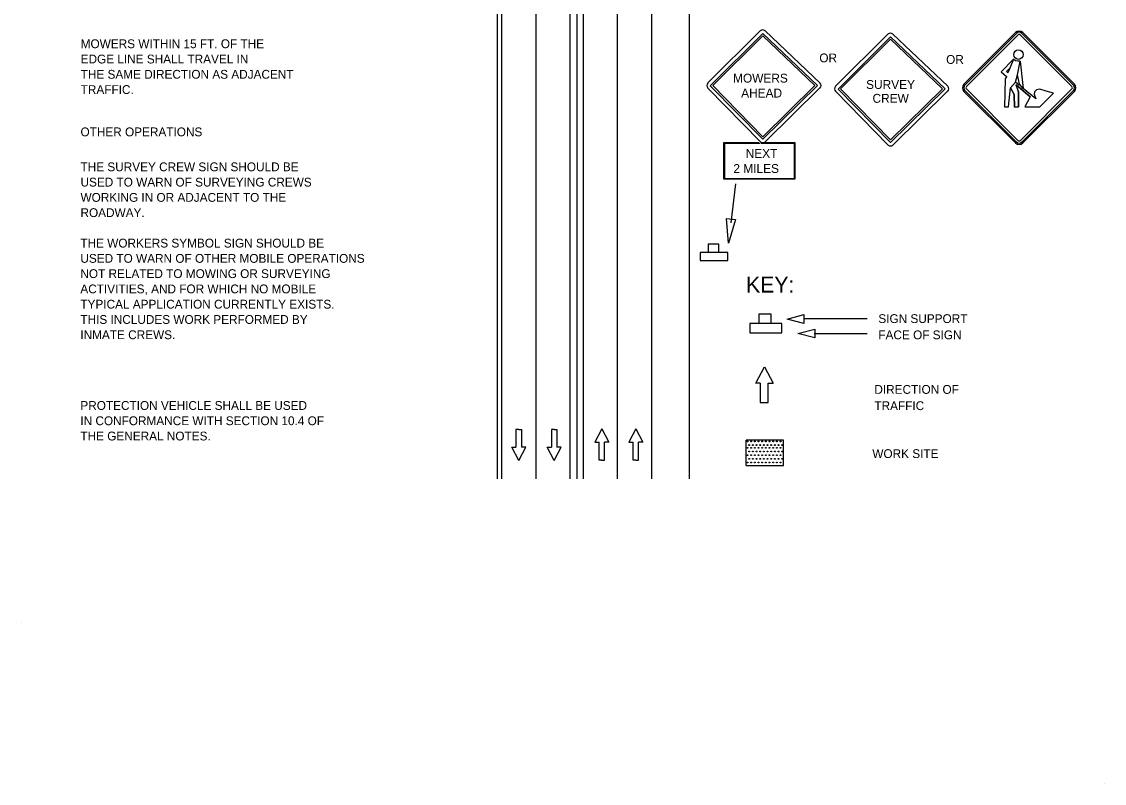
# Model space of a CAD drawing. Extents: x 612.48 to 619.85, y 611.03 to 621.01.
# Drawn here: x 612.48 to 619.85, y 611.03 to 616.22 of the extents above; entities that cross this region are included whole.
import ezdxf

# ---------------------------------------------------------------- set-up
doc = ezdxf.new("R2010")
doc.units = 0
for name, color, linetype in [('DETL-DIMS', 7, 'Continuous'), ('DETL-LINE', 7, 'Continuous'), ('DETL-NOTE', 7, 'Continuous'), ('DETL-TITL', 7, 'Continuous'), ('TTLB-TEXT', 7, 'Continuous'), ('USER-BORD', 7, 'Continuous')]:
    doc.layers.add(name, color=color, linetype=linetype)

# ---------------------------------------------------------------- blocks, each defined once
blk = doc.blocks.new('DIR2')
at = {"layer": 'USER-BORD'}
for p, q in [((0, 0.0012), (-0.0342, -0.0477)), ((0, 0.0012), (0.0342, -0.0477)), ((-0.0342, -0.0477), (-0.0132, -0.0477)), ((-0.0132, -0.1133), (-0.0132, -0.0477)), ((0.0342, -0.0477), (0.0132, -0.0477)), ((0.0132, -0.1133), (0.0132, -0.0477)), ((-0.0011, -0.1133), (-0.0132, -0.1133)), ((-0.0011, -0.1133), (0.0011, -0.1133)), ((0.0011, -0.1133), (0.0132, -0.1133))]:
    blk.add_line(p, q, dxfattribs=at)
blk = doc.blocks.new('SIGN13')
at = {"layer": 'USER-BORD'}
for points in [[(-0.0134, 0.0182), (0.011, 0.0189), (0.011, 0.0371), (-0.0134, 0.0371)], [(-0.0314, 0.0182), (-0.0314, 0), (0.032, 0), (0.032, 0.0182)]]:
    blk.add_lwpolyline(points, close=True, dxfattribs=at)

msp = doc.modelspace()

# ---------------------------------------------------------------- linework, layer by layer
at = {"layer": 'DETL-DIMS'}
for p, q in [((617.3134, 614.8477), (617.3463, 615.1133)), ((617.8054, 614.1954), (618.2386, 614.1954)), ((617.8782, 614.0935), (618.2386, 614.0935))]:
    msp.add_line(p, q, dxfattribs=at)
for points in [[(617.2954, 614.7097), (617.2833, 614.8772), (617.3434, 614.8707)], [(617.6944, 614.1919), (617.8081, 614.2221), (617.8081, 614.1618)], [(617.7687, 614.0935), (617.8825, 614.1236), (617.8825, 614.0633)]]:
    msp.add_lwpolyline(points, close=True, dxfattribs=at)
at = {"layer": 'DETL-LINE'}
for p, q in [((615.7225, 619.9558), (615.7225, 613.1041)), ((615.7516, 619.9558), (615.7516, 613.1041)), ((615.9841, 619.9558), (615.9841, 613.1041)), ((616.2167, 619.9558), (616.2167, 613.1041)), ((616.2629, 619.9564), (616.2629, 613.1045)), ((616.2629, 619.9564), (616.2629, 613.1045)), ((616.306, 619.9564), (616.306, 613.1045)), ((616.5386, 619.9564), (616.5386, 613.1045)), ((616.771, 619.9564), (616.771, 613.1045)), ((617.0282, 619.9564), (617.0282, 615.9413)), ((619.2491, 616.1426), (618.8986, 615.792)), ((619.2555, 616.1368), (618.9049, 615.7857)), ((619.6435, 615.7857), (619.2929, 616.1368)), ((619.6499, 615.792), (619.2993, 616.1426)), ((618.9149, 615.7757), (619.266, 616.1262)), ((619.2821, 616.1262), (619.2824, 616.1262)), ((619.633, 615.7757), (619.2824, 616.1262)), ((619.2824, 616.1262), (619.633, 615.7757)), ((619.2824, 616.1262), (619.633, 615.7757)), ((617.0282, 615.9413), (617.0282, 613.1045)), ((619.1515, 615.8753), (619.2352, 615.9608)), ((619.1515, 615.8753), (619.2352, 615.9608)), ((619.2352, 615.9608), (619.2107, 615.8999)), ((619.2503, 615.9511), (619.2352, 615.9608)), ((619.2651, 615.9489), (619.2503, 615.9511)), ((619.263, 615.854), (619.2816, 615.9489)), ((619.263, 615.854), (619.2816, 615.9489)), ((619.2816, 615.9489), (619.2651, 615.9489)), ((619.2816, 615.9489), (619.3018, 615.7619)), ((619.1515, 615.8753), (619.1879, 615.8427)), ((619.2107, 615.8999), (619.1875, 615.8779)), ((619.1875, 615.8779), (619.2107, 615.8999)), ((619.2107, 615.8999), (619.1875, 615.8779)), ((619.1961, 615.8698), (619.1875, 615.8779)), ((619.2107, 615.8999), (619.198, 615.8687)), ((619.2503, 615.8044), (619.263, 615.854)), ((619.2756, 615.792), (619.263, 615.854)), ((619.266, 615.4081), (618.9149, 615.7587)), ((619.2025, 615.6363), (619.2159, 615.7655)), ((619.2744, 615.7853), (619.2503, 615.8044)), ((619.35, 615.7061), (619.2528, 615.7871)), ((619.2756, 615.792), (619.2744, 615.7853)), ((619.633, 615.7587), (619.2824, 615.4081)), ((619.3885, 615.6905), (619.3018, 615.7619)), ((618.8986, 615.7418), (619.2491, 615.3912)), ((618.9049, 615.7482), (619.2555, 615.3976)), ((619.2929, 615.3976), (619.6435, 615.7482)), ((619.2993, 615.3912), (619.6499, 615.7418)), ((619.35, 615.7061), (619.3127, 615.6363)), ((619.3797, 615.7397), (619.3774, 615.7239)), ((619.3774, 615.7239), (619.3885, 615.6905)), ((619.3916, 615.7523), (619.3797, 615.7397)), ((619.4143, 615.7569), (619.3916, 615.7523)), ((619.457, 615.744), (619.4143, 615.7569)), ((619.4143, 615.6366), (619.5072, 615.7305)), ((619.5072, 615.7305), (619.457, 615.744)), ((619.3127, 615.6363), (619.4143, 615.6366)), ((617.2623, 615.3928), (617.2623, 615.146)), ((617.5021, 615.3928), (617.2623, 615.3928)), ((617.7502, 615.3928), (617.5284, 615.3928)), ((617.7502, 615.146), (617.7502, 615.3928)), ((617.2678, 615.3868), (617.2678, 615.1492)), ((617.5116, 615.3868), (617.2678, 615.3868)), ((617.7447, 615.3868), (617.5189, 615.3868)), ((617.7447, 615.1492), (617.7447, 615.3868)), ((617.2623, 615.146), (617.7502, 615.146)), ((617.2678, 615.1492), (617.7447, 615.1492)), ((617.4817, 613.7553), (617.5406, 613.8663)), ((617.5406, 613.8663), (617.5998, 613.7553)), ((617.5105, 613.7546), (617.4808, 613.7546)), ((617.5105, 613.7546), (617.5105, 613.6236)), ((617.5667, 613.6236), (617.5667, 613.7546)), ((617.5667, 613.7546), (617.5998, 613.7546)), ((617.5105, 613.6236), (617.5667, 613.6236)), ((617.6694, 613.3679), (617.4154, 613.3679)), ((617.6694, 613.3679), (617.4154, 613.3679)), ((617.6694, 613.3679), (617.4154, 613.3679)), ((617.6694, 613.3679), (617.4154, 613.3679)), ((617.4155, 613.1939), (617.4155, 613.368)), ((617.4155, 613.194), (617.4155, 613.368)), ((617.424, 613.359), (617.424, 613.359)), ((617.4248, 613.359), (617.4248, 613.359)), ((617.4368, 613.3342), (617.4368, 613.3342)), ((617.4368, 613.3342), (617.4368, 613.3342)), ((617.4496, 613.359), (617.4496, 613.359)), ((617.4496, 613.359), (617.4496, 613.359)), ((617.4616, 613.3342), (617.4616, 613.3342)), ((617.4616, 613.3342), (617.4616, 613.3342)), ((617.4744, 613.359), (617.4744, 613.359)), ((617.4752, 613.359), (617.4752, 613.359)), ((617.4872, 613.3342), (617.4872, 613.3342)), ((617.4872, 613.3342), (617.4872, 613.3342)), ((617.4992, 613.359), (617.4992, 613.359)), ((617.5, 613.359), (617.5, 613.359)), ((617.512, 613.3342), (617.512, 613.3342)), ((617.512, 613.3342), (617.512, 613.3342)), ((617.524, 613.359), (617.524, 613.359)), ((617.5248, 613.359), (617.5248, 613.359)), ((617.5368, 613.3342), (617.5368, 613.3342)), ((617.5368, 613.3342), (617.5368, 613.3342)), ((617.5496, 613.359), (617.5496, 613.359)), ((617.5496, 613.359), (617.5496, 613.359)), ((617.5616, 613.3342), (617.5616, 613.3342)), ((617.5616, 613.3342), (617.5616, 613.3342)), ((617.5744, 613.359), (617.5744, 613.359)), ((617.5744, 613.359), (617.5744, 613.359)), ((617.5864, 613.3342), (617.5864, 613.3342)), ((617.5864, 613.3342), (617.5864, 613.3342)), ((617.5992, 613.359), (617.5992, 613.359)), ((617.6, 613.359), (617.6, 613.359)), ((617.612, 613.3342), (617.612, 613.3342)), ((617.612, 613.3342), (617.612, 613.3342)), ((617.624, 613.359), (617.624, 613.359)), ((617.6248, 613.359), (617.6248, 613.359)), ((617.6368, 613.3342), (617.6368, 613.3342)), ((617.6368, 613.3342), (617.6368, 613.3342)), ((617.6496, 613.359), (617.6496, 613.359)), ((617.6496, 613.359), (617.6496, 613.359)), ((617.6616, 613.3342), (617.6616, 613.3342)), ((617.6616, 613.3342), (617.6616, 613.3342)), ((617.6694, 613.1939), (617.6694, 613.3679)), ((617.6694, 613.1939), (617.6694, 613.3679)), ((617.6694, 613.1939), (617.6694, 613.3679)), ((617.6694, 613.1939), (617.6694, 613.3679)), ((617.424, 613.3152), (617.424, 613.3152)), ((617.424, 613.2648), (617.424, 613.2648)), ((617.4248, 613.3152), (617.4248, 613.3152)), ((617.4248, 613.2648), (617.4248, 613.2648)), ((617.4368, 613.2896), (617.4368, 613.2896)), ((617.4496, 613.3152), (617.4496, 613.3152)), ((617.4496, 613.3152), (617.4496, 613.3152)), ((617.4496, 613.2648), (617.4496, 613.2648)), ((617.4496, 613.2648), (617.4496, 613.2648)), ((617.4616, 613.2896), (617.4616, 613.2896)), ((617.4744, 613.3152), (617.4744, 613.3152)), ((617.4744, 613.2648), (617.4744, 613.2648)), ((617.4752, 613.3152), (617.4752, 613.3152)), ((617.4752, 613.2648), (617.4752, 613.2648)), ((617.4872, 613.2896), (617.4872, 613.2896)), ((617.4992, 613.3152), (617.4992, 613.3152)), ((617.4992, 613.2648), (617.4992, 613.2648)), ((617.5, 613.3152), (617.5, 613.3152)), ((617.5, 613.2648), (617.5, 613.2648)), ((617.512, 613.2896), (617.512, 613.2896)), ((617.524, 613.3152), (617.524, 613.3152)), ((617.524, 613.2648), (617.524, 613.2648)), ((617.5248, 613.3152), (617.5248, 613.3152)), ((617.5248, 613.2648), (617.5248, 613.2648)), ((617.5368, 613.2896), (617.5368, 613.2896)), ((617.5496, 613.3152), (617.5496, 613.3152)), ((617.5496, 613.3152), (617.5496, 613.3152)), ((617.5496, 613.2648), (617.5496, 613.2648)), ((617.5496, 613.2648), (617.5496, 613.2648)), ((617.5616, 613.2896), (617.5616, 613.2896)), ((617.5744, 613.3152), (617.5744, 613.3152)), ((617.5744, 613.3152), (617.5744, 613.3152)), ((617.5744, 613.2648), (617.5744, 613.2648)), ((617.5744, 613.2648), (617.5744, 613.2648)), ((617.5864, 613.2896), (617.5864, 613.2896)), ((617.5992, 613.3152), (617.5992, 613.3152)), ((617.5992, 613.2648), (617.5992, 613.2648)), ((617.6, 613.3152), (617.6, 613.3152)), ((617.6, 613.2648), (617.6, 613.2648)), ((617.612, 613.2896), (617.612, 613.2896)), ((617.624, 613.3152), (617.624, 613.3152)), ((617.624, 613.2648), (617.624, 613.2648)), ((617.6248, 613.3152), (617.6248, 613.3152)), ((617.6248, 613.2648), (617.6248, 613.2648)), ((617.6368, 613.2896), (617.6368, 613.2896)), ((617.6496, 613.3152), (617.6496, 613.3152)), ((617.6496, 613.3152), (617.6496, 613.3152)), ((617.6496, 613.2648), (617.6496, 613.2648)), ((617.6496, 613.2648), (617.6496, 613.2648)), ((617.6616, 613.2896), (617.6616, 613.2896)), ((617.4155, 613.1939), (617.6695, 613.1939)), ((617.424, 613.2156), (617.424, 613.2156)), ((617.4248, 613.2156), (617.4248, 613.2156)), ((617.4368, 613.24), (617.4368, 613.24)), ((617.4368, 613.24), (617.4368, 613.24)), ((617.4496, 613.2156), (617.4496, 613.2156)), ((617.4496, 613.2156), (617.4496, 613.2156)), ((617.4616, 613.24), (617.4616, 613.24)), ((617.4616, 613.24), (617.4616, 613.24)), ((617.4744, 613.2156), (617.4744, 613.2156)), ((617.4752, 613.2156), (617.4752, 613.2156)), ((617.4872, 613.24), (617.4872, 613.24)), ((617.4872, 613.24), (617.4872, 613.24)), ((617.4992, 613.2156), (617.4992, 613.2156)), ((617.5, 613.2156), (617.5, 613.2156)), ((617.512, 613.24), (617.512, 613.24)), ((617.512, 613.24), (617.512, 613.24)), ((617.524, 613.2156), (617.524, 613.2156)), ((617.5248, 613.2156), (617.5248, 613.2156)), ((617.5368, 613.24), (617.5368, 613.24)), ((617.5368, 613.24), (617.5368, 613.24)), ((617.5496, 613.2156), (617.5496, 613.2156)), ((617.5496, 613.2156), (617.5496, 613.2156)), ((617.5616, 613.24), (617.5616, 613.24)), ((617.5616, 613.24), (617.5616, 613.24)), ((617.5744, 613.2156), (617.5744, 613.2156)), ((617.5744, 613.2156), (617.5744, 613.2156)), ((617.5864, 613.24), (617.5864, 613.24)), ((617.5864, 613.24), (617.5864, 613.24)), ((617.5992, 613.2156), (617.5992, 613.2156)), ((617.6, 613.2156), (617.6, 613.2156)), ((617.612, 613.24), (617.612, 613.24)), ((617.612, 613.24), (617.612, 613.24)), ((617.624, 613.2156), (617.624, 613.2156)), ((617.6248, 613.2156), (617.6248, 613.2156)), ((617.6368, 613.24), (617.6368, 613.24)), ((617.6368, 613.24), (617.6368, 613.24)), ((617.6496, 613.2156), (617.6496, 613.2156)), ((617.6496, 613.2156), (617.6496, 613.2156)), ((617.6616, 613.24), (617.6616, 613.24)), ((617.6616, 613.24), (617.6616, 613.24))]:
    msp.add_line(p, q, dxfattribs=at)
for points in [[(615.9841, 616.2058), (615.9841, 616.1058)], [(616.5386, 616.2064), (616.5386, 616.1064)], [(617.5112, 616.1539), (617.1554, 615.7999)], [(617.1722, 615.7807), (617.5286, 616.1365)], [(617.5286, 616.1365), (617.9006, 615.7825)], [(617.9192, 615.7993), (617.5454, 616.1545)], [(618.3805, 616.1315), (618.0247, 615.7775)], [(618.7885, 615.7769), (618.4147, 616.1321)], [(617.1896, 615.7819), (617.5286, 616.1209)], [(617.5286, 616.1209), (617.8838, 615.7819)], [(618.0415, 615.7583), (618.3979, 616.1141)], [(618.0589, 615.7595), (618.3979, 616.0985)], [(618.3979, 616.1141), (618.7699, 615.7601)], [(618.3979, 616.0985), (618.7531, 615.7595)], [(619.1879, 615.8437), (619.1871, 615.8412), (619.1793, 615.8277), (619.1743, 615.6363), (619.2025, 615.6363)], [(615.9841, 615.8058), (615.9841, 615.7058)], [(616.5386, 615.8064), (616.5386, 615.7064)], [(617.1542, 615.7651), (617.5112, 615.4003)], [(617.5292, 615.4177), (617.1722, 615.7807)], [(617.5292, 615.4339), (617.1896, 615.7819)], [(617.9006, 615.7825), (617.5292, 615.4177)], [(617.8838, 615.7819), (617.5292, 615.4339)], [(617.5472, 615.4009), (617.918, 615.7657)], [(618.3985, 615.4115), (618.0589, 615.7595)], [(618.7699, 615.7601), (618.3985, 615.3953)], [(618.7531, 615.7595), (618.3985, 615.4115)], [(619.3018, 615.7619), (619.2756, 615.792), (619.275, 615.7886), (619.2744, 615.7853), (619.2503, 615.8044), (619.2159, 615.7655), (619.2408, 615.7221), (619.2435, 615.6356), (619.2687, 615.6363), (619.2692, 615.7384), (619.2528, 615.7871), (619.35, 615.7061)], [(619.252, 615.7866), (619.2692, 615.7384), (619.2687, 615.6363), (619.2435, 615.6356), (619.2408, 615.7221), (619.2159, 615.7655), (619.2159, 615.767)], [(618.0235, 615.7427), (618.3805, 615.3779)], [(618.3985, 615.3953), (618.0415, 615.7583)], [(618.4165, 615.3785), (618.7873, 615.7433)], [(615.9841, 615.4058), (615.9841, 615.3058)], [(616.5386, 615.4064), (616.5386, 615.3064)], [(615.9841, 615.0058), (615.9841, 614.9058)], [(616.5386, 615.0064), (616.5386, 614.9064)], [(615.9841, 614.6058), (615.9841, 614.5058)], [(616.5386, 614.6064), (616.5386, 614.5064)], [(615.9841, 614.2058), (615.9841, 614.1058)], [(616.5386, 614.2064), (616.5386, 614.1064)], [(615.9841, 613.8058), (615.9841, 613.7058)], [(616.5386, 613.8064), (616.5386, 613.7064)], [(615.9841, 613.4058), (615.9841, 613.3058)], [(616.5386, 613.4064), (616.5386, 613.3064)]]:
    msp.add_lwpolyline(points, dxfattribs=at)
for centre, radius in [((619.2694, 615.9928), 0.0324), ((617.4248, 613.359), 0.00291), ((617.4368, 613.3342), 0.00291), ((617.4496, 613.359), 0.00291), ((617.4616, 613.3342), 0.00291), ((617.4752, 613.359), 0.00291), ((617.4872, 613.3342), 0.00291), ((617.5, 613.359), 0.00291), ((617.512, 613.3342), 0.00291), ((617.5248, 613.359), 0.00291), ((617.5368, 613.3342), 0.00291), ((617.5496, 613.359), 0.00291), ((617.5616, 613.3342), 0.00291), ((617.5744, 613.359), 0.00291), ((617.5864, 613.3342), 0.00291), ((617.6, 613.359), 0.00291), ((617.612, 613.3342), 0.00291), ((617.6248, 613.359), 0.00291), ((617.6368, 613.3342), 0.00291), ((617.6496, 613.359), 0.00291), ((617.6616, 613.3342), 0.00291), ((617.4248, 613.3153), 0.00291), ((617.4248, 613.2649), 0.00291), ((617.4368, 613.2897), 0.00291), ((617.4496, 613.3153), 0.00291), ((617.4496, 613.2649), 0.00291), ((617.4616, 613.2897), 0.00291), ((617.4752, 613.3153), 0.00291), ((617.4752, 613.2649), 0.00291), ((617.4872, 613.2897), 0.00291), ((617.5, 613.3153), 0.00291), ((617.5, 613.2649), 0.00291), ((617.512, 613.2897), 0.00291), ((617.5248, 613.3153), 0.00291), ((617.5248, 613.2649), 0.00291), ((617.5368, 613.2897), 0.00291), ((617.5496, 613.3153), 0.00291), ((617.5496, 613.2649), 0.00291), ((617.5616, 613.2897), 0.00291), ((617.5744, 613.3153), 0.00291), ((617.5744, 613.2649), 0.00291), ((617.5864, 613.2897), 0.00291), ((617.6, 613.3153), 0.00291), ((617.6, 613.2649), 0.00291), ((617.612, 613.2897), 0.00291), ((617.6248, 613.3153), 0.00291), ((617.6248, 613.2649), 0.00291), ((617.6368, 613.2897), 0.00291), ((617.6496, 613.3153), 0.00291), ((617.6496, 613.2649), 0.00291), ((617.6616, 613.2897), 0.00291), ((617.4248, 613.2156), 0.00291), ((617.4368, 613.2401), 0.00291), ((617.4496, 613.2156), 0.00291), ((617.4616, 613.2401), 0.00291), ((617.4752, 613.2156), 0.00291), ((617.4872, 613.2401), 0.00291), ((617.5, 613.2156), 0.00291), ((617.512, 613.2401), 0.00291), ((617.5248, 613.2156), 0.00291), ((617.5368, 613.2401), 0.00291), ((617.5496, 613.2156), 0.00291), ((617.5616, 613.2401), 0.00291), ((617.5744, 613.2156), 0.00291), ((617.5864, 613.2401), 0.00291), ((617.6, 613.2156), 0.00291), ((617.612, 613.2401), 0.00291), ((617.6248, 613.2156), 0.00291), ((617.6368, 613.2401), 0.00291), ((617.6496, 613.2156), 0.00291), ((617.6616, 613.2401), 0.00291)]:
    msp.add_circle(centre, radius, dxfattribs=at)
for centre, radius, start, end in [((617.5287, 616.1367), 0.0244, 47.72631, 133.5312), ((618.3979, 616.1143), 0.0244, 47.72631, 133.5312), ((619.2738, 616.118), 0.0354, 45, 135), ((619.2738, 616.118), 0.0266, 45, 135), ((619.2738, 616.118), 0.0118, 45, 135), ((617.1728, 615.7818), 0.0244, 135, 222.51045), ((617.9014, 615.7825), 0.0244, 315, 45), ((618.042, 615.7595), 0.0244, 135, 222.51045), ((618.7705, 615.7602), 0.0244, 315, 45), ((618.9236, 615.7671), 0.0354, 135, 225), ((618.9235, 615.7672), 0.0266, 135, 225), ((618.9235, 615.7672), 0.0118, 135, 225), ((619.6248, 615.7672), 0.0118, 315, 45), ((619.6248, 615.7672), 0.0266, 315, 45), ((619.6248, 615.7672), 0.0354, 315, 45), ((617.5294, 615.4173), 0.0244, 220.60129, 315), ((619.2741, 615.4166), 0.0354, 225, 315), ((619.2741, 615.4166), 0.0266, 225, 315), ((619.2741, 615.4166), 0.0118, 225, 315), ((618.3986, 615.395), 0.0244, 220.60129, 315)]:
    msp.add_arc(centre, radius, start, end, dxfattribs=at)
at = {"layer": 'TTLB-TEXT'}
for p, q in [((612.485, 612.1276), (612.485, 612.1276)), ((619.854, 611.0304), (619.854, 611.0304))]:
    msp.add_line(p, q, dxfattribs=at)

# ---------------------------------------------------------------- block references
at = {"layer": 'DETL-LINE'}
for name, p, xscale, yscale in [('SIGN13', (617.1969, 614.5913), 2.980410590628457, 2.980410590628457), ('SIGN13', (617.5488, 614.0988), 3.4385190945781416, 3.438519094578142), ('DIR2', (616.4338, 613.4422), 1.395105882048, 1.860141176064), ('DIR2', (616.666, 613.4422), 1.395105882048, 1.860141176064)]:
    msp.add_blockref(name, p, dxfattribs=dict(at, xscale=xscale, yscale=yscale))
at = {"layer": 'DETL-LINE', "xscale": 1.395105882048, "yscale": 1.860141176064, "rotation": 180}
for p in [(615.868, 613.2301), (616.1085, 613.2301)]:
    msp.add_blockref('DIR2', p, dxfattribs=at)

# ---------------------------------------------------------------- texts
at = {"layer": 'DETL-LINE'}
for s, p in [('MOWERS', (617.3269, 615.8022)), ('AHEAD', (617.3821, 615.7007)), ('NEXT', (617.4129, 615.2897)), ('2 MILES', (617.3291, 615.1868))]:
    msp.add_text(s, height=0.06048, dxfattribs=at).set_placement(p)
at = {"layer": 'DETL-NOTE'}
for s, height, p in [('MOWERS WITHIN 15 FT. OF THE', 0.06, (612.8867, 616.0366)), ('EDGE LINE SHALL TRAVEL IN', 0.06, (612.8867, 615.9326)), ('OR', 0.06, (617.9142, 615.9402)), ('OR', 0.06, (618.7771, 615.9298)), ('THE SAME DIRECTION AS ADJACENT', 0.06, (612.8867, 615.8286)), ('TRAFFIC.', 0.06, (612.8867, 615.7246)), ('SURVEY', 0.06048, (618.2325, 615.7589)), ('CREW', 0.06048, (618.2762, 615.6647)), ('OTHER OPERATIONS', 0.06, (612.8855, 615.4365)), ('THE SURVEY CREW SIGN SHOULD BE', 0.06, (612.8855, 615.1985)), ('USED TO WARN OF SURVEYING CREWS', 0.06, (612.8855, 615.0945)), ('WORKING IN OR ADJACENT TO THE', 0.06, (612.8855, 614.9905)), ('ROADWAY.', 0.06, (612.8855, 614.8865)), ('THE WORKERS SYMBOL SIGN SHOULD BE', 0.06, (612.8846, 614.6792)), ('USED TO WARN OF OTHER MOBILE OPERATIONS', 0.06, (612.8846, 614.5752)), ('NOT RELATED TO MOWING OR SURVEYING', 0.06, (612.8846, 614.4712)), ('ACTIVITIES, AND FOR WHICH NO MOBILE', 0.06, (612.8846, 614.3672)), ('TYPICAL APPLICATION CURRENTLY EXISTS.', 0.06, (612.8846, 614.2632)), ('THIS INCLUDES WORK PERFORMED BY', 0.06, (612.8846, 614.1592)), ('SIGN SUPPORT', 0.06, (618.3159, 614.1649)), ('INMATE CREWS.', 0.06, (612.8846, 614.0552)), ('FACE OF SIGN', 0.06, (618.3159, 614.0542)), ('DIRECTION OF', 0.06, (618.2889, 613.6829)), ('PROTECTION VEHICLE SHALL BE USED', 0.06, (612.8846, 613.5735)), ('TRAFFIC', 0.06, (618.2889, 613.5722)), ('IN CONFORMANCE WITH SECTION 10.4 OF', 0.06, (612.8846, 613.4695)), ('THE GENERAL NOTES.', 0.06, (612.8846, 613.3655)), ('WORK SITE', 0.06, (618.2748, 613.2456))]:
    msp.add_text(s, height=height, dxfattribs=at).set_placement(p)
at = {"layer": 'DETL-TITL'}
msp.add_text('KEY:', height=0.108, dxfattribs=at).set_placement((617.4155, 614.3727))

doc.saveas('drawing.dxf')
